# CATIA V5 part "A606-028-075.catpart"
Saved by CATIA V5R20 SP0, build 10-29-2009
Part number: A606-028-075
Source: Unknown
Property "ARTICLENO": "A606-028-075"
Property "BOMINFO": "A606-028-075"
Property "CODE": "A606-028-075"
Property "HOLES": "2"
Property "L": "75.000"
Property "L1": "15.000"
Property "L2": "45.000"
Property "LINA": "A606-028-075"
Property "NB": "A606-028-075"
Property "NBSYN": "$CODE."
Property "NN": "A606"
Property "NT": "Wear Plates, self-lubricating"
Property "SCREW": "2xM6"
Property "SUPPLIER": "CF"
Property "W": "28.000"
Bounding box of the stored display mesh (mm): x -14 to 14, y -5 to 5, z -37.5 to 37.5
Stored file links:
  C:\Users\Utente\Desktop\3D files A606\A606-028-075.catpart

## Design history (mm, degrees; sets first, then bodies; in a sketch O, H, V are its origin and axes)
Body1 "Geometry.1" (main body)
  Solid1 "A606-028-075.catpart": solid without history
